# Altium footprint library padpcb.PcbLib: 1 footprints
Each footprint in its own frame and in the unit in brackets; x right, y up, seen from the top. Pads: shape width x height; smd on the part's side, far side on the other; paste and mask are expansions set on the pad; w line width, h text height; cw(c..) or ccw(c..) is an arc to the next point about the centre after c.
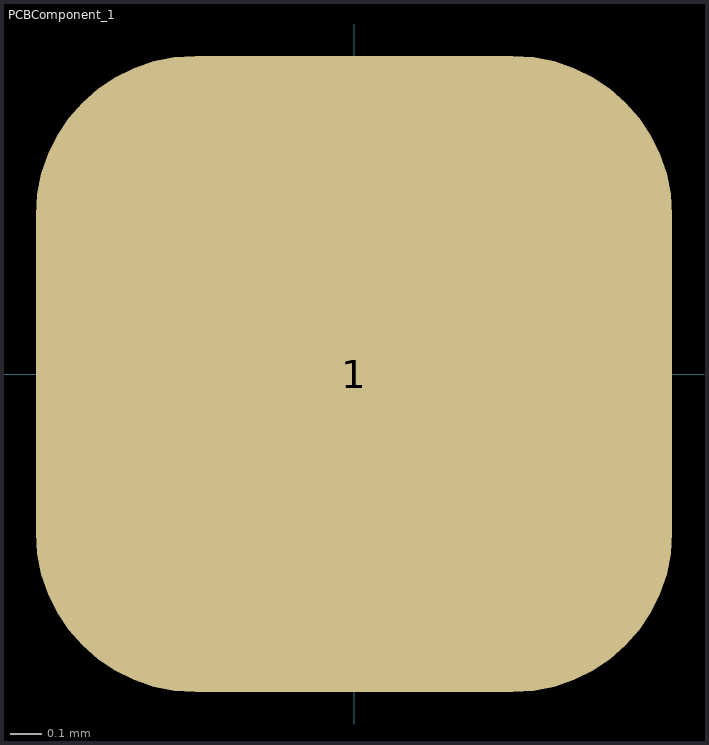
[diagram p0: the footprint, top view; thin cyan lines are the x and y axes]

## PCBComponent_1 [mm]
pads (1):
  rrect50% 2x2 / inner rrect50% 2x2 / far side rrect50% 0x0 all layers, no hole paste-2539.97 mask+0.127: 1(0,0)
